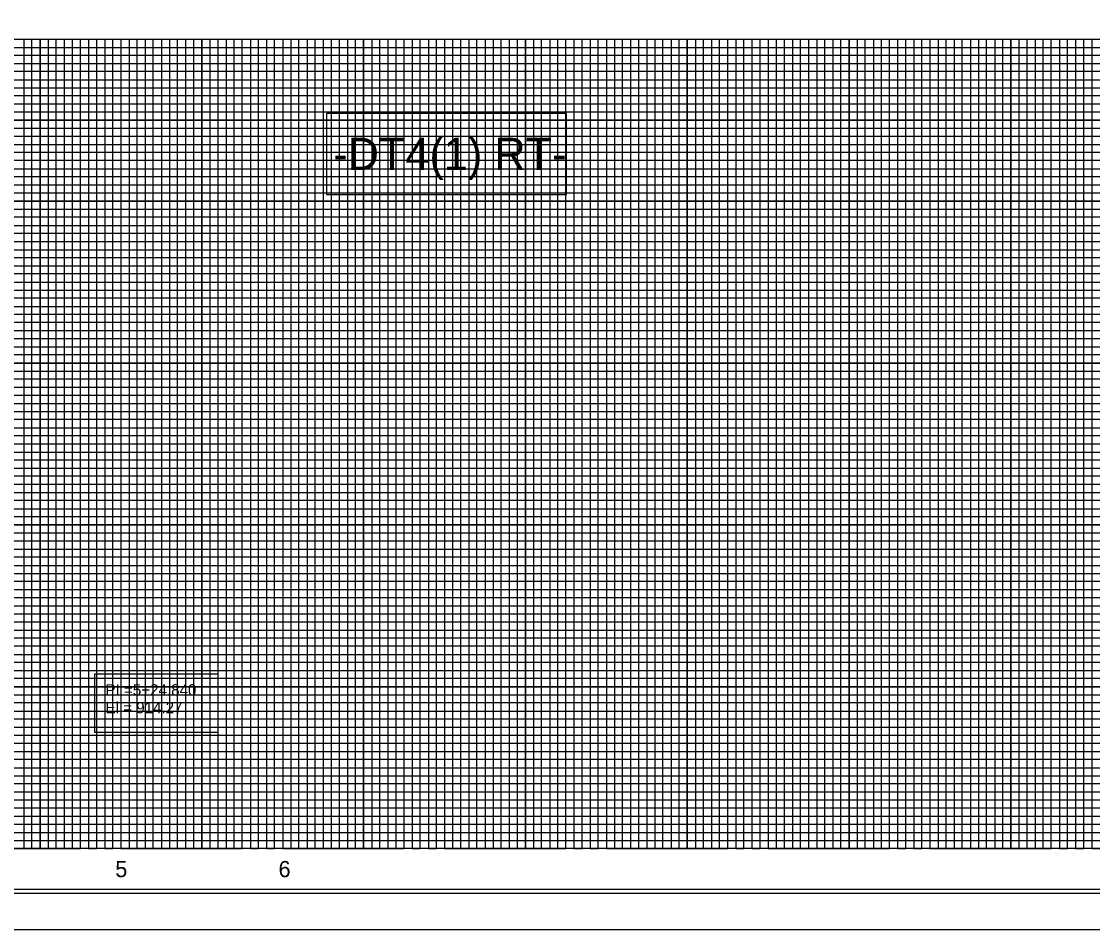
# Model space of a CAD drawing. Extents: x 1648123 to 1650776, y 802691 to 803791.
# Drawn here: x 1649518 to 1650180, y 802691 to 803252 of the extents above; entities that cross this region are included whole.
import ezdxf

# ---------------------------------------------------------------- set-up
doc = ezdxf.new("R2010")
doc.units = 0
for name, color, linetype in [('Exist Vertical Profile Horizontal Axis Label Major', 7, 'Continuous'), ('Prop Grid Mask', 7, 'Continuous'), ('Prop VPI Ditch Grade Right Label', 7, 'Continuous'), ('Sheet Cutting Line CELL', 7, 'Continuous'), ('Sheet DOT Grid CELL', 7, 'Continuous'), ('Sheet Layout Profile Border Port 2', 7, 'Continuous'), ('Sheet Plot Border Inside CELL', 7, 'Continuous'), ('Sheet Plot Border Outside CELL', 7, 'Continuous'), ('Sheet Profile CELL', 7, 'Continuous'), ('Sheet Profile Grid Major CELL', 7, 'Continuous'), ('Sheet Profile Grid Middle CELL', 7, 'Continuous'), ('Sheet Profile Grid Minor CELL', 7, 'Continuous')]:
    doc.layers.add(name, color=color, linetype=linetype)

msp = doc.modelspace()

# ---------------------------------------------------------------- linework, layer by layer
at = {"layer": 'Prop Grid Mask'}
for points in [[(1649706.35, 803195.18), (1649706.35, 803145.18), (1649854.56, 803145.18), (1649854.56, 803195.18)], [(1649562.96, 802848.76), (1649562.96, 802812.98), (1649639.3, 802812.98), (1649639.3, 802848.76)]]:
    msp.add_lwpolyline(points, close=True, dxfattribs=at)
at = {"layer": 'Sheet Cutting Line CELL'}
msp.add_line((1648862.28, 802691.02), (1650546.28, 802691.02), dxfattribs=at)
at = {"layer": 'Sheet DOT Grid CELL'}
for p, q in [((1649029.28, 803241.02), (1650529.17, 803241.02)), ((1649529.28, 803241.02), (1649529.28, 802741.02)), ((1649579.28, 803241.02), (1649579.28, 802741.02)), ((1649629.28, 803241.02), (1649629.28, 802741.02)), ((1649679.28, 803241.02), (1649679.28, 802741.02)), ((1649729.28, 803241.02), (1649729.28, 802741.02)), ((1649779.28, 803241.02), (1649779.28, 802741.02)), ((1649829.28, 803241.02), (1649829.28, 802741.02)), ((1649879.28, 803241.02), (1649879.28, 802741.02)), ((1649929.28, 803241.02), (1649929.28, 802741.02)), ((1649979.28, 803241.02), (1649979.28, 802741.02)), ((1650029.28, 803241.02), (1650029.28, 802741.02)), ((1650079.28, 803241.02), (1650079.28, 802741.02)), ((1650129.28, 803241.02), (1650129.28, 802741.02)), ((1650179.28, 803241.02), (1650179.28, 802741.02)), ((1649029.28, 803191.02), (1650529.17, 803191.02)), ((1649029.28, 803141.02), (1650529.17, 803141.02)), ((1649029.28, 803091.02), (1650529.17, 803091.02)), ((1649029.28, 803041.02), (1650529.17, 803041.02)), ((1649029.28, 802991.02), (1650529.17, 802991.02)), ((1649029.28, 802941.02), (1650529.17, 802941.02)), ((1649029.28, 802891.02), (1650529.17, 802891.02)), ((1649029.28, 802841.02), (1650529.17, 802841.02)), ((1649029.28, 802791.02), (1650529.17, 802791.02))]:
    msp.add_line(p, q, dxfattribs=at)
at = {"layer": 'Sheet Layout Profile Border Port 2'}
msp.add_lwpolyline([(1649079.28, 803241.02), (1650479.28, 803241.02), (1650479.28, 802741.02), (1649079.28, 802741.02)], close=True, dxfattribs=at)
at = {"layer": 'Sheet Plot Border Inside CELL'}
msp.add_lwpolyline([(1648875.28, 802713.47), (1650541.78, 802713.47), (1650541.78, 803768.57), (1648875.28, 803768.57)], close=True, dxfattribs=at)
at = {"layer": 'Sheet Plot Border Outside CELL'}
msp.add_lwpolyline([(1648862.28, 802691.02), (1650546.28, 802691.02), (1650546.28, 803791.02), (1648862.28, 803791.02)], close=True, dxfattribs=at)
at = {"layer": 'Sheet Profile CELL'}
for p, q in [((1649029.28, 803241.02), (1650529.28, 803241.02)), ((1650529.28, 802741.02), (1649029.28, 802741.02)), ((1649029.28, 802716.02), (1650529.28, 802716.02))]:
    msp.add_line(p, q, dxfattribs=at)
msp.add_lwpolyline([(1650529.28, 803766.02), (1649029.28, 803766.02), (1649029.28, 802716.02), (1650529.28, 802716.02)], close=True, dxfattribs=at)
at = {"layer": 'Sheet Profile Grid Major CELL'}
for p, q in [((1649529.28, 803241.02), (1649579.28, 803241.02)), ((1649629.28, 803241.02), (1649679.28, 803241.02)), ((1649729.28, 803241.02), (1649779.28, 803241.02)), ((1649829.28, 803241.02), (1649879.28, 803241.02)), ((1649929.28, 803241.02), (1649979.28, 803241.02)), ((1650029.28, 803241.02), (1650079.28, 803241.02)), ((1650129.28, 803241.02), (1650179.28, 803241.02))]:
    msp.add_line(p, q, dxfattribs=at)
for points in [[(1649479.28, 802741.02), (1649529.28, 802741.02), (1649529.28, 803241.02), (1649579.28, 803241.02), (1649579.28, 802741.02), (1649629.28, 802741.02), (1649629.28, 803241.02), (1649679.28, 803241.02), (1649679.28, 802741.02), (1649729.28, 802741.02), (1649729.28, 803241.02), (1649779.28, 803241.02), (1649779.28, 802741.02), (1649829.28, 802741.02), (1649829.28, 803241.02), (1649879.28, 803241.02), (1649879.28, 802741.02), (1649929.28, 802741.02), (1649929.28, 803241.02), (1649979.28, 803241.02), (1649979.28, 802741.02), (1650029.28, 802741.02), (1650029.28, 803241.02), (1650079.28, 803241.02), (1650079.28, 802741.02), (1650129.28, 802741.02), (1650129.28, 803241.02), (1650179.28, 803241.02), (1650179.28, 802741.02), (1650229.28, 802741.02)], [(1650529.28, 803191.02), (1649029.28, 803191.02)], [(1650529.28, 803141.02), (1649029.28, 803141.02), (1649029.28, 803091.02), (1650529.28, 803091.02)], [(1650529.28, 803041.02), (1649029.28, 803041.02), (1649029.28, 802991.02), (1650529.28, 802991.02)], [(1650529.28, 802941.02), (1649029.28, 802941.02), (1649029.28, 802891.02), (1650529.28, 802891.02)], [(1650529.28, 802841.02), (1649029.28, 802841.02), (1649029.28, 802841.02), (1649029.28, 802791.02), (1650529.28, 802791.02)], [(1650529.28, 802741.02), (1649029.28, 802741.02)]]:
    msp.add_lwpolyline(points, dxfattribs=at)
at = {"layer": 'Sheet Profile Grid Middle CELL'}
for points in [[(1649504.28, 802741.02), (1649554.28, 802741.02), (1649554.28, 803241.02), (1649604.28, 803241.02), (1649604.28, 802741.02), (1649654.28, 802741.02), (1649654.28, 802741.02), (1649654.28, 803241.02), (1649704.28, 803241.02), (1649704.28, 802741.02), (1649754.28, 802741.02), (1649754.28, 803241.02), (1649804.28, 803241.02), (1649804.28, 802741.02), (1649854.28, 802741.02), (1649854.28, 803241.02), (1649904.28, 803241.02), (1649904.28, 802741.02), (1649954.28, 802741.02), (1649954.28, 803241.02), (1650004.28, 803241.02), (1650004.28, 802741.02), (1650054.28, 802741.02), (1650054.28, 803241.02), (1650104.28, 803241.02), (1650104.28, 802741.02), (1650154.28, 802741.02), (1650154.28, 803241.02), (1650204.28, 803241.02)], [(1649029.28, 803216.02), (1650529.28, 803216.02)], [(1650529.28, 803166.02), (1649029.28, 803166.02), (1649029.28, 803116.02), (1650529.28, 803116.02)], [(1650529.28, 803066.02), (1649029.28, 803066.02), (1649029.28, 803016.02), (1650529.28, 803016.02)], [(1650529.28, 802966.02), (1649029.28, 802966.02), (1649029.28, 802916.02), (1650529.28, 802916.02)], [(1650529.28, 802866.02), (1649029.28, 802866.02), (1649029.28, 802816.02), (1650529.28, 802816.02)], [(1650529.28, 802766.02), (1649029.28, 802766.02)]]:
    msp.add_lwpolyline(points, dxfattribs=at)
at = {"layer": 'Sheet Profile Grid Minor CELL'}
for p, q in [((1649079.28, 803236.02), (1650479.28, 803236.02)), ((1650479.28, 803231.02), (1649079.28, 803231.02)), ((1649079.28, 803226.02), (1650479.28, 803226.02)), ((1650479.28, 803221.02), (1649079.28, 803221.02)), ((1649079.28, 803211.02), (1650479.28, 803211.02)), ((1650479.28, 803206.02), (1649079.28, 803206.02)), ((1649079.28, 803201.02), (1650479.28, 803201.02)), ((1650479.28, 803196.02), (1649079.28, 803196.02)), ((1649079.28, 803186.02), (1650479.28, 803186.02)), ((1650479.28, 803181.02), (1649079.28, 803181.02)), ((1649079.28, 803176.02), (1650479.28, 803176.02)), ((1650479.28, 803171.02), (1649079.28, 803171.02)), ((1649079.28, 803161.02), (1650479.28, 803161.02)), ((1650479.28, 803156.02), (1649079.28, 803156.02)), ((1649079.28, 803151.02), (1650479.28, 803151.02)), ((1650479.28, 803146.02), (1649079.28, 803146.02)), ((1649079.28, 803136.02), (1650479.28, 803136.02)), ((1650479.28, 803131.02), (1649079.28, 803131.02)), ((1649079.28, 803126.02), (1650479.28, 803126.02)), ((1650479.28, 803121.02), (1649079.28, 803121.02)), ((1649079.28, 803111.02), (1650479.28, 803111.02)), ((1650479.28, 803106.02), (1649079.28, 803106.02)), ((1649079.28, 803101.02), (1650479.28, 803101.02)), ((1650479.28, 803096.02), (1649079.28, 803096.02)), ((1649079.28, 803086.02), (1650479.28, 803086.02)), ((1650479.28, 803081.02), (1649079.28, 803081.02)), ((1649079.28, 803076.02), (1650479.28, 803076.02)), ((1650479.28, 803071.02), (1649079.28, 803071.02)), ((1649079.28, 803061.02), (1650479.28, 803061.02)), ((1650479.28, 803056.02), (1649079.28, 803056.02)), ((1649079.28, 803051.02), (1650479.28, 803051.02)), ((1650479.28, 803046.02), (1649079.28, 803046.17)), ((1649079.28, 803036.02), (1650479.28, 803036.02)), ((1650479.28, 803031.02), (1649079.28, 803031.02)), ((1649079.28, 803026.02), (1650479.28, 803026.02)), ((1650479.28, 803021.02), (1649079.28, 803021.02)), ((1649079.28, 803011.02), (1650479.28, 803011.02)), ((1650479.28, 803006.02), (1649079.28, 803006.02)), ((1649079.28, 803001.02), (1650479.28, 803001.02)), ((1650479.28, 802996.02), (1649079.28, 802996.02)), ((1649079.28, 802986.02), (1650479.28, 802986.02)), ((1650479.28, 802981.02), (1649079.28, 802981.02)), ((1649079.28, 802976.02), (1650479.28, 802976.02)), ((1650479.28, 802971.02), (1649079.28, 802971.02)), ((1649079.28, 802961.02), (1650479.28, 802961.02)), ((1650479.28, 802956.02), (1649079.28, 802956.02)), ((1649079.28, 802951.02), (1650479.28, 802951.02)), ((1650479.28, 802946.02), (1649079.28, 802946.02)), ((1649079.28, 802936.02), (1650479.28, 802936.02)), ((1650479.28, 802931.02), (1649079.28, 802931.02)), ((1649079.28, 802926.02), (1650479.28, 802926.02)), ((1650479.28, 802921.02), (1649079.28, 802921.02)), ((1649079.28, 802911.02), (1650479.28, 802911.02)), ((1650479.28, 802906.02), (1649079.28, 802906.02)), ((1649079.28, 802901.02), (1650479.28, 802901.02)), ((1650479.28, 802896.02), (1649079.28, 802896.02)), ((1649079.28, 802886.02), (1650479.28, 802886.02)), ((1650479.28, 802881.02), (1649079.28, 802881.02)), ((1649079.28, 802876.02), (1650479.28, 802876.02)), ((1650479.28, 802871.02), (1649079.28, 802871.02)), ((1649079.28, 802861.02), (1650479.28, 802861.02)), ((1650479.28, 802856.02), (1649079.28, 802856.02)), ((1649079.28, 802851.02), (1650479.28, 802851.02)), ((1650479.28, 802846.02), (1649079.28, 802846.02)), ((1649079.28, 802836.02), (1650479.28, 802836.02)), ((1650479.28, 802831.02), (1649079.28, 802831.02)), ((1649079.28, 802826.02), (1650479.28, 802826.02)), ((1650479.28, 802821.02), (1649079.28, 802821.02)), ((1649079.28, 802811.02), (1650479.28, 802811.02)), ((1650479.28, 802806.02), (1649079.28, 802806.02)), ((1649079.28, 802801.02), (1650479.28, 802801.02)), ((1650479.28, 802796.02), (1649079.28, 802796.02)), ((1649079.28, 802786.02), (1650479.28, 802786.02)), ((1650479.28, 802781.02), (1649079.28, 802781.02)), ((1649079.28, 802776.02), (1650479.28, 802776.02)), ((1650479.28, 802771.02), (1649079.28, 802771.02)), ((1649079.28, 802761.02), (1650479.28, 802761.02)), ((1650479.28, 802756.02), (1649079.28, 802756.02)), ((1649079.28, 802751.02), (1650479.28, 802751.02)), ((1649079.28, 802746.02), (1650479.28, 802746.02))]:
    msp.add_line(p, q, dxfattribs=at)
for points in [[(1649514.28, 803241.02), (1649519.28, 803241.02), (1649519.28, 802741.02), (1649524.28, 802741.02), (1649524.28, 803241.02), (1649534.28, 803241.02), (1649534.28, 802741.02), (1649539.28, 802741.02), (1649539.28, 803241.02), (1649544.28, 803241.02), (1649544.28, 802741.02), (1649549.28, 802741.02), (1649549.28, 803241.02), (1649559.28, 803241.02), (1649559.28, 802741.02), (1649564.28, 802741.02), (1649564.28, 803241.02), (1649569.28, 803241.02), (1649569.28, 802741.02), (1649574.28, 802741.02), (1649574.28, 803241.02), (1649584.28, 803241.02), (1649584.28, 802741.02), (1649589.28, 802741.02), (1649589.28, 803241.02), (1649594.28, 803241.02), (1649594.28, 802741.02), (1649599.28, 802741.02), (1649599.28, 803241.02), (1649609.28, 803241.02)], [(1649609.28, 803241.02), (1649609.28, 802741.02), (1649614.28, 802741.02), (1649614.28, 803241.02), (1649619.28, 803241.02), (1649619.28, 802741.02), (1649624.28, 802741.02), (1649624.28, 803241.02), (1649634.28, 803241.02), (1649634.28, 802741.02), (1649639.28, 802741.02), (1649639.28, 803241.02), (1649644.28, 803241.02), (1649644.28, 802741.02), (1649649.28, 802741.02), (1649649.28, 803241.02), (1649659.28, 803241.02), (1649659.28, 802741.02), (1649664.28, 802741.02), (1649664.28, 803241.02), (1649669.28, 803241.02), (1649669.28, 802741.02), (1649674.28, 802741.02), (1649674.28, 803241.02), (1649684.28, 803241.02), (1649684.28, 802741.02), (1649689.28, 802741.02), (1649689.28, 803241.02), (1649694.28, 803241.02), (1649694.28, 802741.02), (1649699.28, 802741.02), (1649699.28, 803241.02), (1649709.28, 803241.02), (1649709.28, 802741.02), (1649714.28, 802741.02), (1649714.28, 803241.02), (1649719.28, 803241.02), (1649719.28, 802741.02), (1649724.28, 802741.02), (1649724.28, 803241.02), (1649734.28, 803241.02), (1649734.28, 802741.02), (1649734.28, 802741.02), (1649739.28, 802741.02), (1649739.28, 803241.02), (1649744.28, 803241.02), (1649744.28, 802741.02), (1649749.28, 802741.02), (1649749.28, 803241.02), (1649759.28, 803241.02), (1649759.28, 802741.02), (1649764.28, 802741.02), (1649764.28, 803241.02), (1649769.28, 803241.02), (1649769.28, 802741.02), (1649774.28, 802741.02), (1649774.28, 803241.02), (1649784.28, 803241.02), (1649784.28, 802741.02), (1649789.28, 802741.02), (1649789.28, 803241.02), (1649794.28, 803241.02), (1649794.28, 802741.02), (1649799.28, 802741.02), (1649799.28, 803241.02), (1649809.28, 803241.02), (1649809.28, 802741.02), (1649814.28, 802741.02), (1649814.28, 803241.02), (1649819.28, 803241.02), (1649819.28, 802741.02), (1649824.28, 802741.02), (1649824.28, 803241.02), (1649834.28, 803241.02), (1649834.28, 802741.02), (1649839.28, 802741.02), (1649839.28, 803241.02), (1649844.28, 803241.02), (1649844.28, 802741.02), (1649849.28, 802741.02), (1649849.28, 803241.02), (1649859.28, 803241.02), (1649859.28, 802741.02), (1649864.28, 802741.02), (1649864.28, 803241.02), (1649869.28, 803241.02), (1649869.28, 802741.02), (1649874.28, 802741.02), (1649874.28, 803241.02), (1649884.28, 803241.02), (1649884.28, 802741.02), (1649888.98, 802741.57), (1649889.28, 802741.02), (1649889.28, 803241.02), (1649894.28, 803241.02), (1649894.28, 802741.02), (1649899.28, 802741.02), (1649899.28, 803241.02), (1649909.28, 803241.02), (1649909.28, 802741.02), (1649914.28, 802741.02)], [(1649914.28, 802741.02), (1649914.28, 803241.02), (1649919.28, 803241.02), (1649919.28, 802741.02), (1649924.28, 802741.02), (1649924.28, 803241.02), (1649934.28, 803241.02), (1649934.28, 802741.02), (1649939.28, 802741.02), (1649939.28, 803241.02), (1649944.28, 803241.02), (1649944.28, 802741.02), (1649949.28, 802741.02), (1649949.28, 803241.02), (1649959.28, 803241.02), (1649959.28, 802741.02), (1649964.28, 802741.02), (1649964.28, 803241.02), (1649969.28, 803241.02), (1649969.28, 802741.02), (1649974.28, 802741.02), (1649974.28, 803241.02), (1649984.28, 803241.02), (1649984.28, 802741.02), (1649989.28, 802741.02), (1649989.28, 803241.02), (1649994.28, 803241.02), (1649994.28, 802741.02), (1649999.28, 802741.02), (1649999.28, 803241.02), (1650009.28, 803241.02), (1650009.28, 802741.02), (1650014.28, 802741.02), (1650014.28, 803241.02), (1650019.28, 803241.02), (1650019.28, 802741.02), (1650024.28, 802741.02), (1650024.28, 803241.02), (1650034.28, 803241.02), (1650034.28, 802741.02), (1650039.28, 802741.02), (1650039.28, 803241.02), (1650044.28, 803241.02), (1650044.28, 802741.02), (1650049.28, 802741.02), (1650049.28, 803241.02), (1650059.28, 803241.02), (1650059.28, 802741.02), (1650064.28, 802741.02), (1650064.28, 803241.02), (1650069.28, 803241.02), (1650069.28, 802741.02), (1650074.28, 802741.02), (1650074.28, 803241.02), (1650084.28, 803241.02), (1650084.28, 802741.02), (1650089.28, 802741.02), (1650089.28, 803241.02), (1650094.28, 803241.02), (1650094.28, 802741.02), (1650099.28, 802741.02), (1650099.28, 803241.02), (1650109.28, 803241.02), (1650109.28, 802741.02), (1650114.28, 802741.02), (1650114.28, 803241.02), (1650119.28, 803241.02), (1650119.28, 802741.02), (1650124.28, 802741.02), (1650124.28, 803241.02), (1650134.28, 803241.02), (1650134.28, 802741.02), (1650139.28, 802741.02), (1650139.28, 803241.02), (1650144.28, 803241.02), (1650144.28, 802741.02), (1650149.28, 802741.02), (1650149.28, 803241.02), (1650159.28, 803241.02), (1650159.28, 802741.02), (1650164.28, 802741.02), (1650164.28, 803241.02), (1650169.28, 803241.02), (1650169.28, 802741.02), (1650174.28, 802741.02), (1650174.28, 803241.02), (1650184.28, 803241.02)]]:
    msp.add_lwpolyline(points, dxfattribs=at)

# ---------------------------------------------------------------- texts
at = {"layer": 'Exist Vertical Profile Horizontal Axis Label Major'}
for s, height, p in [('-DT4(1) RT-', 20, (1649710.51, 803160.18)), ('5', 10, (1649575.78, 802723.4)), ('6', 10, (1649676.67, 802723.38))]:
    msp.add_text(s, height=height, dxfattribs=at).set_placement(p)
at = {"layer": 'Prop VPI Ditch Grade Right Label'}
for s, p in [('PI =5+24.840', (1649569.72, 802835.58)), ('El = 914.27', (1649569.72, 802824.58))]:
    msp.add_text(s, height=7, dxfattribs=at).set_placement(p)

doc.saveas('drawing.dxf')
